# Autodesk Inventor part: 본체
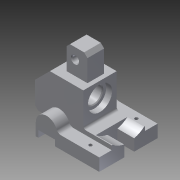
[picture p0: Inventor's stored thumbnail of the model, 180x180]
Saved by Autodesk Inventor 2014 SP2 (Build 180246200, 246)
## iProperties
Created: 2016-11
Part Number: 본체
Material: 알루미늄 6061
Document SubType Name: Modeling
Designer: kb
Density: 2.71 g/cm^3
Appearance: 알루미늄 - 평지
Author: kb
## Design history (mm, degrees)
sketch "스케치1"
  geometry: L1 (0, 0)-(1473.2, 0); L2 (1473.2, 0)-(1473.2, 1219.2); L3 (1473.2, 1219.2)-(457.2, 1219.2); L4 (457.2, 1219.2)-(0, 762); L5 (0, 762)-(0, 0)
  constraints: 10 end point, 2 parallel, 1 horizontal, 1 perpendicular
  dimensions: "d0" = 1473.2 distance between parallel lines of L2 L5; "d1" = 1219.2 distance of L1.end L2.end; "d2" = 45 deg angle of L4 L3; "d3" = 457.2 distance from line of L3.end L5
extrude "돌출1" new body sketch "스케치1" stored distance "d4" = 1016; taper "d5" = 0 deg
sketch "스케치2"
  geometry: L1 (1016, 1016)-(1016, 0) reference; L2 (0, 1016)-(1016, 1016) reference; L3 (254, 762)-(889, 762); L4 (889, 762)-(889, 254); L5 (889, 254)-(254, 254); L6 (254, 254)-(254, 762); L7 (254, 762)-(889, 254); L8 (889, 762)-(254, 254); 2 further points
  constraints: 12 end point, 2 midpoint, 2 parallel, 1 horizontal, 1 perpendicular
  dimensions: "d6" = 635 distance between parallel lines of L4 L6; "d7" = 127 distance between parallel lines of L1 L4; "d8" = 508 distance of L3.end L4.end; "d9" = 508 distance from line of L2 point (571.5, 508)
extrude "돌출2" join sketch "스케치2" distance "d10" = 762; taper "d11" = 0 deg
sketch "스케치3"
  geometry: L1 (0, 0)-(1473.2, 0) reference; L2 (1473.2, 1219.2)-(457.2, 1219.2) reference; L3 (0, 762)-(0, 0) reference; L4 (1167.325, 76.2)-(2339.643, 76.2); L5 (2339.643, 76.2)-(2339.643, -304.8); L6 (2339.643, -304.8)-(993.443, -304.8); L7 (993.443, -304.8)-(993.443, -127); L8 (993.443, -127)-(485.443, -127); L9 (485.443, -127)-(485.443, -332.99); L10 (485.443, -332.99)-(409.243, -332.99); L11 (409.243, -332.99)-(409.243, 42.113); A1 r 330.2 centre (739.443, 42.113) between (1048.469, 158.454) and (409.243, 42.113); A2 r 127 centre (1167.325, 203.2) between (1048.469, 158.454) and (1167.325, 76.2); 1 further point
  constraints: 16 end point, 5 parallel, 5 point on circle, 3 perpendicular, 2 centre point, 2 tangent, 1 point on line
  dimensions: "d44" = 1524 distance between parallel lines of L6 L2; "d45" = 381 distance between parallel lines of L6 L4; "d46" = 508 distance between parallel lines of L7 L9; "d47" = 76.2 distance between parallel lines of L9 L11; "d48" = 1600.2 distance from line of L5 A1.centre; "d49" = 127 radius of A2; "d50" = 177.8 distance between parallel lines of L6 L8; "d51" = 330.2 radius of A1
sketch "스케치4"
  geometry: L1 (0, 0)-(1473.2, 0) reference; L2 (1473.2, -1016)-(0, -1016) reference; L3 (1473.2, -1016)-(0, -1016) reference; L4 (0, -1016)-(0, 0) reference; L5 (0, 0)-(1473.2, 0) reference; L6 (1473.2, 0)-(1473.2, -1016) reference; L7 (1473.2, -1016)-(2286, -1016); L8 (2286, -1016)-(2286, 0); L9 (2286, 0)-(1473.2, 0); L10 (1473.2, 0)-(1473.2, -1016); 1 further point
  constraints: 8 end point, 2 parallel, 1 horizontal, 1 perpendicular, 1 point on line
  dimensions: "d12" = 812.8 distance of L7.start L7.end; "d13" = 0 distance between parallel lines of L7 L2; "d14" = 0 distance between parallel lines of L1 L9
extrude "돌출3" join sketch "스케치4" distance "d15" = 127; taper "d17" = 0 deg; dims "d16" = 381, "d18" = 0
hole "구멍1" diameter "d21" = 203.2; stored, may be unused: countersink angle "d25" = 82 deg, drill point angle "d27" = 118 deg; dims "d19" = 254.508, "d20" = 330.2, "d22" = 19.05, "d23" = 9.525, "d24" = 6.35, "d26" = 25.4
hole "구멍2" diameter "d30" = 508; stored, may be unused: countersink angle "d34" = 82 deg, drill point angle "d36" = 118 deg; dims "d28" = 457.2, "d29" = 508, "d31" = 19.05, "d32" = 736.6, "d33" = 177.8, "d35" = 25.4
chamfer "모따기1" distance "d37" = 25.4; stored, may be unused: second distance "d38" = 3.175, angle "d39" = 45 deg
node "작업 평면1"
sketch "스케치5"
  geometry: L1 (0, -1092.2)-(1016, -1092.2) reference; L2 (1016, -1092.2)-(1016, -1600.2) reference; L3 (1016, -1600.2)-(0, -1600.2) reference; L4 (0, -1600.2)-(0, -1092.2) reference; C1 r 368.3 at (508, -457.2) reference; C2 r 736.6 at (508, -457.2); 1 further point
  constraints: 1 centre point, 1 coincident
  dimensions: "d41" = 1473.2 diameter of C2
extrude "돌출4" cut sketch "스케치5" distance "d42" = 762; taper "d43" = 0 deg
extrude "돌출5" join sketch "스케치3" distance "d52" = 381; taper "d53" = 0 deg
sketch "스케치7"
  geometry: L1 (-102.897, 546.245)-(1572.755, 546.245); L2 (1572.755, 546.245)-(1572.755, -1376.101); L3 (1572.755, -1376.101)-(-102.897, -1376.101); L4 (-102.897, -1376.101)-(-102.897, 546.245); 1 further point
  constraints: 8 end point, 2 parallel, 1 horizontal, 1 perpendicular
extrude "돌출6" cut sketch "스케치7" distance "d54" = 477.8375; taper "d55" = 0 deg
sketch "스케치8"
  geometry: L1 (1292.557, -1397)-(479.757, -1397) reference; L2 (1346.2, -381)-(1346.2, 0) reference; L3 (1292.557, -381)-(1346.2, -381); L4 (1346.2, -381)-(1346.2, -1397); L5 (1346.2, -1397)-(1292.557, -1397); L6 (479.757, -381)-(479.757, -1397) reference; L7 (479.757, -381)-(1292.557, -381) reference; L8 (1292.557, -1397)-(479.757, -1397) reference; L9 (1346.2, -381)-(479.757, -381); L10 (479.757, -381)-(479.757, -1397); L11 (479.757, -1397)-(1346.2, -1397); L12 (1346.2, -1397)-(1346.2, -381); 1 further point
  constraints: 14 end point, 3 parallel, 2 horizontal, 2 perpendicular
  dimensions: "d56" = 0 distance between parallel lines of L2 L4; "d57" = 0 distance between parallel lines of L5 L1
extrude "돌출7" join sketch "스케치8" distance "d58" = 508; taper "d59" = 0 deg
sketch "스케치9"
  geometry: C1 r 368.3 at (508, -457.2) reference; C2 r 279.4 at (508, -457.2) reference; C3 r 736.6 at (508, -457.2); 1 further point
  constraints: 1 centre point, 1 coincident
  dimensions: "d60" = 1473.2 diameter of C3
extrude "돌출8" cut sketch "스케치9" distance "d61" = 762; taper "d62" = 0 deg
chamfer "모따기2" distance "d63" = 25.4; stored, may be unused: second distance "d64" = 3.175, angle "d65" = 45 deg
hole "구멍3" diameter "d68" = 101.6; stored, may be unused: countersink angle "d72" = 82 deg, drill point angle "d74" = 118 deg; dims "d66" = 457.2, "d67" = 190.5, "d69" = 19.05, "d70" = 736.6, "d71" = 177.8, "d73" = 25.4
chamfer "모따기3" distance "d75" = 101.6; stored, may be unused: second distance "d76" = 3.175, angle "d77" = 45 deg
chamfer "모따기4" distance "d78" = 101.6; stored, may be unused: second distance "d79" = 3.175, angle "d80" = 45 deg
fillet "모깎기1" dims "d81" = 76.2
sketch "스케치11"
  geometry: L1 (28.081, -1016)-(987.919, -1016) reference; L2 (379.533, -1016)-(684.333, -1016); L3 (684.333, -1016)-(684.333, -1524); L4 (684.333, -1524)-(379.533, -1524); L5 (379.533, -1524)-(379.533, -1016); 1 further point
  constraints: 8 end point, 2 parallel, 1 horizontal, 1 perpendicular, 1 point on line
  dimensions: "d87" = 304.8 distance between parallel lines of L3 L5; "d88" = 508 distance between parallel lines of L4 L1
extrude "돌출10" cut sketch "스케치11" distance "d89" = 762; taper "d90" = 0 deg
sketch "스케치12"
  geometry: L1 (101.6, 0)-(0, 101.6) reference; L2 (101.6, 0)-(409.243, 0) reference; L3 (409.243, 0)-(409.243, 42.113) reference; L4 (2339.643, 76.2)-(1167.325, 76.2) reference; L5 (2339.643, 76.2)-(2339.643, 203.2) reference; L6 (1549.4, 203.2)-(2339.643, 203.2) reference; L7 (1473.2, 279.4)-(1473.2, 1219.2) reference; L8 (1473.2, 1219.2)-(457.2, 1219.2) reference; L9 (457.2, 1219.2)-(0, 762) reference; L10 (0, 762)-(0, 101.6) reference; A1 r 330.2 centre (739.443, 42.113) between (1048.469, 158.454) and (409.243, 42.113) reference; A2 r 127 centre (1167.325, 203.2) between (1048.469, 158.454) and (1167.325, 76.2) reference; A3 r 76.2 centre (1549.4, 279.4) between (1473.2, 279.4) and (1549.4, 203.2) reference; 1 further point
node "솔리드1"
mirror "대칭1"
mirror "대칭2"
node "투영된 루프1"
node "절단 모서리 투영1"
node "절단 모서리 투영2"
other parameters: "d40" = 355.6
